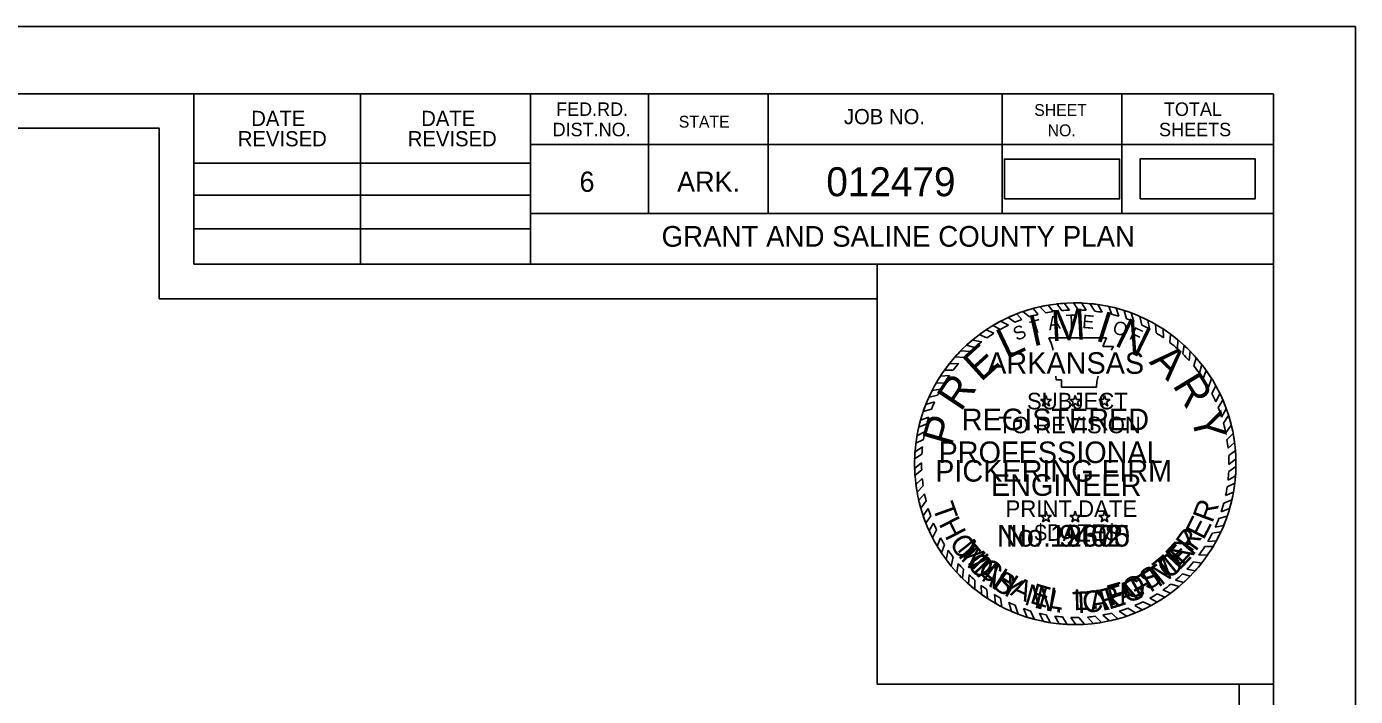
# Model space of a CAD drawing. Extents: x 10700 to 22009, y 10612 to 15552.
# Drawn here: x 16875 to 17646, y 15164 to 15552 of the extents above; entities that cross this region are included whole.
import ezdxf

# ---------------------------------------------------------------- set-up
doc = ezdxf.new("R2010")
doc.units = 0
for name, color, linetype in [('Default', 7, 'Continuous'), ('R_Border', 7, 'Continuous'), ('R_Border Notes', 7, 'Continuous'), ('R_No Plot', 7, 'Continuous'), ('STAMP_PE_CRAFTON', 7, 'Continuous'), ('STAMP_PE_FOSTER', 7, 'Continuous'), ('STAMP_PE_SEAL-INFO', 7, 'Continuous'), ('STAMP_PE_TAEGTMEYER', 7, 'Continuous'), ('STAMP_PE_TXT', 7, 'Continuous'), ('STAMP_PRELIMINARY', 7, 'Continuous')]:
    doc.layers.add(name, color=color, linetype=linetype)

msp = doc.modelspace()

# ---------------------------------------------------------------- linework, layer by layer
at = {"layer": 'Default'}
for points in [[(17442.16, 15452.18), (17508.99, 15452.18), (17508.99, 15475.28), (17442.16, 15475.28)], [(17520.86, 15452.28), (17587.69, 15452.28), (17587.69, 15475.38), (17520.86, 15475.38)]]:
    msp.add_lwpolyline(points, close=True, dxfattribs=at)
at = {"layer": 'R_Border'}
for p, q in [((14436.47, 15513.13), (17598.27, 15513.13)), ((16971.87, 15414.33), (16971.87, 15513.13)), ((17068.67, 15414.33), (17068.67, 15513.13)), ((17167.27, 15513.13), (17167.27, 15414.33)), ((17235.67, 15513.13), (17235.67, 15443.73)), ((17305.07, 15513.13), (17305.07, 15443.73)), ((17440.87, 15513.13), (17440.87, 15443.73)), ((17510.27, 15513.13), (17510.27, 15443.73)), ((17598.27, 13458.53), (17598.27, 15513.13)), ((17598.27, 15483.73), (17167.27, 15483.73)), ((17598.27, 15483.93), (17598.27, 15483.93)), ((16971.87, 15472.93), (17167.27, 15472.93)), ((16971.87, 15454.33), (17167.27, 15454.33)), ((17598.27, 15443.73), (17167.27, 15443.73)), ((17196.87, 15443.73), (17598.27, 15443.73)), ((16971.87, 15434.93), (17167.27, 15434.93)), ((17598.27, 15414.33), (16971.87, 15414.33))]:
    msp.add_line(p, q, dxfattribs=at)
at = {"layer": 'R_No Plot'}
msp.add_line((14312.47, 15552.08), (17645.8, 15552.08), dxfattribs=at)
for points in [[(14312.4, 15552.08), (17645.8, 15552.08), (17645.8, 13418.7), (14312.4, 13418.7)], [(14456.47, 15493.13), (16951.87, 15493.13), (16951.87, 15394.33), (17127.27, 15394.33), (17368.27, 15394.33), (17368.27, 15171.01), (17578.27, 15171.01), (17578.27, 13478.53), (14456.47, 13478.53)], [(17578.27, 14505.83), (14456.47, 14505.83), (14456.47, 15493.13), (16951.87, 15493.13), (16951.87, 15394.33), (17127.27, 15394.33), (17368.27, 15394.33), (17368.27, 15171.01), (17578.27, 15171.01)], [(17368.27, 15414.33), (17598.27, 15414.33), (17598.27, 15171.01), (17368.27, 15171.01)]]:
    msp.add_lwpolyline(points, close=True, dxfattribs=at)
at = {"layer": 'STAMP_PE_SEAL-INFO'}
for p, q in [((17452.87, 15386.89), (17456.68, 15383.83)), ((17458.78, 15388.71), (17461.66, 15385.23)), ((17462.66, 15389.68), (17466.22, 15386.25)), ((17467.48, 15390.64), (17470.47, 15386.97)), ((17472.64, 15391.38), (17475.45, 15387.55)), ((17479.99, 15387.83), (17476.87, 15391.77)), ((17484.97, 15387.88), (17482.18, 15391.98)), ((17489.55, 15387.67), (17486.97, 15391.91)), ((17494.61, 15387.17), (17491.69, 15391.61)), ((17498.87, 15386.52), (17496.29, 15391.07)), ((17504.49, 15385.33), (17502.75, 15389.93)), ((17508.5, 15384.25), (17506.91, 15388.94)), ((17513.02, 15382.78), (17511.61, 15387.57)), ((17440, 15381.34), (17444.64, 15379.08)), ((17444.31, 15383.45), (17448.21, 15380.71)), ((17449.39, 15385.61), (17452.34, 15382.35)), ((17517.21, 15381.18), (17515.76, 15386.14)), ((17521.82, 15379.13), (17520.79, 15384.1)), ((17526.28, 15376.83), (17525.41, 15381.92)), ((17530.15, 15374.57), (17529.76, 15379.57)), ((17427.45, 15373.72), (17432.01, 15371.68)), ((17431.66, 15376.39), (17436.07, 15374.37)), ((17435.52, 15378.83), (17439.85, 15376.6)), ((17468, 15371.67), (17501.45, 15371.67)), ((17469.22, 15368.6), (17468, 15371.67)), ((17501.45, 15371.67), (17499.2, 15366.75)), ((17534.5, 15371.71), (17534.19, 15376.86)), ((17538.1, 15369.04), (17538.45, 15373.91)), ((17416.89, 15364.22), (17422.33, 15363.81)), ((17420.25, 15367.45), (17424.83, 15366.06)), ((17423.68, 15370.45), (17428.98, 15369.45)), ((17470.26, 15365.62), (17469.22, 15368.6)), ((17470.33, 15364.48), (17470.26, 15365.62)), ((17499.2, 15366.75), (17505.52, 15366.75)), ((17505.52, 15366.75), (17504.07, 15364.48)), ((17542.57, 15365.31), (17542.76, 15370.54)), ((17545.69, 15362.39), (17546.39, 15367.37)), ((17549.28, 15358.66), (17549.95, 15363.92)), ((17410.21, 15356.66), (17415.7, 15356.88)), ((17413.66, 15360.77), (17418.88, 15360.39)), ((17552.02, 15355.49), (17553.39, 15360.2)), ((17555.26, 15351.32), (17556.61, 15356.31)), ((17405.08, 15349.52), (17410.24, 15349.86)), ((17407.43, 15352.96), (17412.48, 15352.91)), ((17472.24, 15347.39), (17471.98, 15349.56)), ((17496.62, 15349.56), (17495.84, 15346.47)), ((17557.46, 15348.17), (17559.24, 15352.8)), ((17400.31, 15341.28), (17405.29, 15341.93)), ((17402.62, 15345.51), (17407.51, 15345.71)), ((17475.38, 15347.39), (17472.24, 15347.39)), ((17475.38, 15343.08), (17475.38, 15347.39)), ((17495.68, 15343.08), (17475.38, 15343.08)), ((17495.84, 15346.47), (17495.68, 15343.08)), ((17560.54, 15343.2), (17562.37, 15348.11)), ((17562.54, 15339.53), (17564.8, 15343.97)), ((17396.59, 15333.07), (17401.63, 15334.53)), ((17398.43, 15337.39), (17403.45, 15338.43)), ((17564.85, 15334.69), (17567.11, 15339.54)), ((17566.25, 15331.32), (17568.89, 15335.65)), ((17393.52, 15323.97), (17398.3, 15325.66)), ((17395.09, 15329), (17399.93, 15330.36)), ((17568.2, 15325.83), (17570.91, 15330.57)), ((17569.28, 15322.18), (17572.21, 15326.71)), ((17392.48, 15319.9), (17397.18, 15321.83)), ((17570.61, 15316.6), (17573.79, 15321.06)), ((17395.26, 15312.85), (17390.81, 15310.62)), ((17396.12, 15317.44), (17391.46, 15314.95)), ((17571.3, 15312.8), (17574.83, 15316.33)), ((17571.96, 15307.7), (17575.69, 15311.06)), ((17394.31, 15304.24), (17390.09, 15301.68)), ((17394.67, 15308.49), (17390.31, 15305.68)), ((17572.28, 15303.52), (17576.18, 15306.44)), ((17394.14, 15299.31), (17390.09, 15295.95)), ((17394.21, 15295.24), (17390.29, 15291.99)), ((17572.3, 15294.29), (17576.49, 15297.06)), ((17572.41, 15298.34), (17576.46, 15301.56)), ((17394.54, 15290.29), (17390.83, 15286.72)), ((17571.39, 15285.34), (17575.82, 15287.54)), ((17571.9, 15289.23), (17576.24, 15291.79)), ((17395.06, 15285.99), (17391.52, 15282.26)), ((17395.85, 15281.4), (17392.45, 15277.73)), ((17570.49, 15280.34), (17575.04, 15282.3)), ((17396.78, 15277.22), (17393.66, 15273.07)), ((17398.02, 15272.75), (17395.07, 15268.57)), ((17567.94, 15270.88), (17572.84, 15272.89)), ((17569.41, 15275.83), (17574.13, 15277.84)), ((17399.43, 15268.51), (17396.61, 15264.4)), ((17401.09, 15264.25), (17398.47, 15260.03)), ((17566.59, 15267.09), (17571.42, 15268.4)), ((17402.81, 15260.41), (17400.53, 15255.81)), ((17405.16, 15255.83), (17403.25, 15250.93)), ((17562.84, 15258.58), (17567.72, 15259.26)), ((17564.45, 15261.94), (17569.33, 15262.91)), ((17407.51, 15251.8), (17405.68, 15247.09)), ((17409.54, 15248.68), (17408.44, 15243.16)), ((17558.4, 15250.79), (17563.18, 15250.73)), ((17560.12, 15253.59), (17565.13, 15254.14)), ((17412.35, 15244.77), (17411.33, 15239.47)), ((17415.39, 15241), (17414.52, 15235.8)), ((17551.93, 15241.91), (17556.54, 15241.11)), ((17555.01, 15245.85), (17560.05, 15245.87)), ((17418.41, 15237.62), (17417.79, 15232.4)), ((17421.64, 15234.37), (17421.34, 15229.08)), ((17545.55, 15234.98), (17549.95, 15233.6)), ((17548.09, 15237.57), (17552.86, 15236.72)), ((17425.08, 15231.24), (17425.05, 15225.95)), ((17428.68, 15228.3), (17428.87, 15223.05)), ((17432.06, 15225.8), (17432.42, 15220.62)), ((17534.17, 15225.59), (17538.56, 15223.69)), ((17538.78, 15229.01), (17543.46, 15227.56)), ((17541.49, 15231.26), (17546.2, 15229.97)), ((17436.33, 15222.98), (17436.94, 15217.86)), ((17439.84, 15220.92), (17440.75, 15215.8)), ((17444.65, 15218.43), (17446.21, 15213.21)), ((17522.51, 15218.73), (17527.35, 15216.61)), ((17526.59, 15220.86), (17530.76, 15218.53)), ((17530.74, 15223.31), (17535.23, 15221.35)), ((17448.37, 15216.74), (17450.1, 15211.63)), ((17453.3, 15214.81), (17455.39, 15209.8)), ((17457.4, 15213.46), (17459.66, 15208.57)), ((17462.47, 15212.08), (17464.6, 15207.42)), ((17466.45, 15211.23), (17468.92, 15206.64)), ((17471.45, 15210.41), (17473.85, 15206.01)), ((17475.82, 15209.94), (17478.56, 15205.65)), ((17480.66, 15209.66), (17483.69, 15205.53)), ((17485.26, 15209.65), (17488.7, 15205.69)), ((17490.45, 15209.91), (17493.71, 15206.12)), ((17494.83, 15210.38), (17498.56, 15206.79)), ((17499.28, 15211.07), (17503.17, 15207.68)), ((17504.21, 15212.12), (17507.99, 15208.87)), ((17508.8, 15213.36), (17512.97, 15210.39)), ((17513.73, 15214.99), (17518.16, 15212.3)), ((17517.92, 15216.63), (17522.15, 15214.03))]:
    msp.add_line(p, q, dxfattribs=at)
for radius, start, end in [(93.23, 105.23389, 109.03519), (93.23, 99.75254, 102.77648), (89.14, 98.25799, 101.03289), (93.23, 93.93815, 96.55172), (89.14, 92.11016, 95.03666), (93.23, 87.72979, 90.67067), (89.14, 85.96279, 88.9097), (93.23, 81.97315, 84.82355), (89.14, 79.92642, 82.69597), (93.23, 75.31251, 77.94263), (93.23, 69.60611, 72.30577), (93.23, 117.65441, 120.80988), (93.23, 111.31242, 114.70259), (89.14, 110.30864, 113.16588), (89.14, 104.03521, 107.36155), (89.14, 73.55748, 76.23144), (89.14, 67.62483, 70.50398), (93.23, 63.13288, 66.2704), (89.14, 61.15575, 64.37837), (93.23, 56.90029, 60.09423), (93.23, 123.61993, 126.59063), (89.14, 121.97456, 125.11001), (89.14, 115.68692, 119.15827), (89.14, 54.92383, 58.27016), (93.23, 50.3492, 53.71593), (93.23, 135.40208, 138.30314), (89.14, 133.13306, 136.25623), (93.23, 129.73259, 132.53764), (89.14, 127.52969, 130.96829), (89.14, 48.30163, 52.03953), (93.23, 44.3405, 47.39292), (93.23, 141.60556, 144.44865), (89.14, 139.30101, 142.58729), (89.14, 42.22116, 45.55119), (93.23, 38.12472, 41.23157), (93.23, 147.00719, 149.89904), (89.14, 145.01972, 148.21036), (89.14, 36.13503, 39.53106), (93.23, 31.96138, 35.42937), (93.23, 152.86398, 155.51889), (89.14, 151.03153, 153.57304), (89.14, 29.90321, 33.66454), (93.23, 25.93909, 29.01247), (93.23, 158.40766, 161.07015), (89.14, 156.34018, 159.23194), (89.14, 23.77322, 27.22114), (93.23, 19.95381, 23.31409), (89.14, 162.43309, 165.00133), (89.14, 17.68022, 21.42509), (93.23, 13.84205, 17.44468), (93.23, 164.3068, 166.89395), (89.14, 11.54445, 15.23639), (93.23, 170.0003, 172.68778), (89.14, 167.90481, 170.90393), (89.14, 5.7599, 9.06056), (93.23, 7.58519, 10.86211), (93.23, 175.74093, 178.2066), (89.14, 173.73, 176.47337), (89.14, 359.73289, 3.06392), (93.23, 1.72155, 4.72681), (93.23, 181.72508, 184.16255), (89.14, 179.64537, 182.26333), (93.23, 355.71562, 358.95694), (93.23, 187.42037, 190.19271), (89.14, 185.45389, 188.23401), (89.14, 353.86319, 357.12742), (93.23, 349.83047, 353.08845), (89.14, 191.22736, 193.98583), (89.14, 348.07782, 351.34355), (93.23, 193.03695, 195.99732), (89.14, 196.96751, 199.83526), (89.14, 341.77699, 345.09248), (93.23, 343.89247, 347.03502), (93.23, 198.89671, 201.62812), (89.14, 202.77613, 205.47915), (89.14, 335.6038, 339.18578), (93.23, 337.38367, 340.99332), (93.23, 204.54793, 207.43282), (89.14, 208.78826, 211.79343), (89.14, 329.55488, 333.20757), (93.23, 331.40371, 334.93315), (93.23, 210.86355, 213.65709), (89.14, 214.18375, 217.27474), (89.14, 323.58513, 327.44069), (93.23, 325.44052, 328.98725), (93.23, 216.61154, 219.49098), (89.14, 220.39088, 223.30564), (89.14, 316.65308, 320.37109), (93.23, 318.28455, 321.80429), (93.23, 222.47995, 225.38008), (89.14, 226.24938, 229.24068), (89.14, 310.77436, 314.31605), (93.23, 312.45177, 315.66328), (93.23, 228.36648, 231.34802), (89.14, 232.22904, 234.93361), (89.14, 304.82299, 308.51428), (93.23, 306.37206, 310.20799), (93.23, 234.29502, 236.94517), (89.14, 238.22227, 240.83529), (93.23, 240.1977, 242.86128), (89.14, 244.32043, 246.94859), (89.14, 292.87452, 296.11851), (89.14, 299.07679, 302.17235), (93.23, 300.62101, 303.87026), (93.23, 246.57598, 249.15579), (89.14, 250.34912, 253.12157), (93.23, 252.59667, 255.32518), (89.14, 256.50505, 259.11916), (89.14, 262.37828, 265.20115), (89.14, 268.3215, 271.27698), (89.14, 274.61565, 277.44863), (89.14, 280.34588, 283.58137), (89.14, 286.64233, 289.97826), (93.23, 288.57086, 291.97334), (93.23, 294.64808, 298.21662), (93.23, 258.44328, 261.13983), (93.23, 264.19784, 267.10092), (93.23, 270.25484, 273.33609), (93.23, 276.42389, 279.43574), (93.23, 282.31994, 285.37019)]:
    msp.add_arc((17483.27, 15298.76), radius, start, end, dxfattribs=at)
at = {"layer": 'STAMP_PE_TXT'}
for p, q in [((17465.07, 15334.47), (17463.09, 15335.91)), ((17463.09, 15335.91), (17465.54, 15335.91)), ((17464.31, 15332.14), (17465.07, 15334.47)), ((17466.3, 15333.58), (17464.31, 15332.14)), ((17465.54, 15335.91), (17466.3, 15338.25)), ((17466.3, 15338.25), (17467.05, 15335.91)), ((17468.28, 15332.14), (17466.3, 15333.58)), ((17467.05, 15335.91), (17469.5, 15335.91)), ((17469.5, 15335.91), (17467.52, 15334.47)), ((17467.52, 15334.47), (17468.28, 15332.14)), ((17482.05, 15334.47), (17480.07, 15335.91)), ((17480.07, 15335.91), (17482.52, 15335.91)), ((17481.29, 15332.14), (17482.05, 15334.47)), ((17483.27, 15333.58), (17481.29, 15332.14)), ((17482.52, 15335.91), (17483.27, 15338.25)), ((17483.27, 15338.25), (17484.03, 15335.91)), ((17485.26, 15332.14), (17483.27, 15333.58)), ((17484.03, 15335.91), (17486.48, 15335.91)), ((17486.48, 15335.91), (17484.5, 15334.47)), ((17484.5, 15334.47), (17485.26, 15332.14)), ((17499.03, 15334.47), (17497.04, 15335.91)), ((17497.04, 15335.91), (17499.5, 15335.91)), ((17498.27, 15332.14), (17499.03, 15334.47)), ((17500.25, 15333.58), (17498.27, 15332.14)), ((17499.5, 15335.91), (17500.25, 15338.25)), ((17500.25, 15338.25), (17501.01, 15335.91)), ((17502.24, 15332.14), (17500.25, 15333.58)), ((17501.01, 15335.91), (17503.46, 15335.91)), ((17503.46, 15335.91), (17501.48, 15334.47)), ((17501.48, 15334.47), (17502.24, 15332.14)), ((17465.07, 15267.4), (17463.09, 15268.84)), ((17463.09, 15268.84), (17465.54, 15268.84)), ((17464.31, 15265.07), (17465.07, 15267.4)), ((17466.3, 15266.51), (17464.31, 15265.07)), ((17465.54, 15268.84), (17466.3, 15271.18)), ((17466.3, 15271.18), (17467.05, 15268.84)), ((17468.28, 15265.07), (17466.3, 15266.51)), ((17467.05, 15268.84), (17469.5, 15268.84)), ((17469.5, 15268.84), (17467.52, 15267.4)), ((17467.52, 15267.4), (17468.28, 15265.07)), ((17482.05, 15267.4), (17480.07, 15268.84)), ((17480.07, 15268.84), (17482.52, 15268.84)), ((17481.29, 15265.07), (17482.05, 15267.4)), ((17483.27, 15266.51), (17481.29, 15265.07)), ((17482.52, 15268.84), (17483.27, 15271.18)), ((17483.27, 15271.18), (17484.03, 15268.84)), ((17485.26, 15265.07), (17483.27, 15266.51)), ((17484.03, 15268.84), (17486.48, 15268.84)), ((17486.48, 15268.84), (17484.5, 15267.4)), ((17484.5, 15267.4), (17485.26, 15265.07)), ((17499.03, 15267.4), (17497.04, 15268.84)), ((17497.04, 15268.84), (17499.5, 15268.84)), ((17498.27, 15265.07), (17499.03, 15267.4)), ((17500.25, 15266.51), (17498.27, 15265.07)), ((17499.5, 15268.84), (17500.25, 15271.18)), ((17500.25, 15271.18), (17501.01, 15268.84)), ((17502.24, 15265.07), (17500.25, 15266.51)), ((17501.01, 15268.84), (17503.46, 15268.84)), ((17503.46, 15268.84), (17501.48, 15267.4)), ((17501.48, 15267.4), (17502.24, 15265.07))]:
    msp.add_line(p, q, dxfattribs=at)
at = {"layer": 'STAMP_PRELIMINARY'}
msp.add_circle((17483.27, 15298.76), 93.23, dxfattribs=at)

# ---------------------------------------------------------------- texts
at = {"layer": 'R_Border'}
for s, height, p in [('DATE', 8.792, (17005.25, 15494.5)), ('DATE', 8.792, (17103.85, 15494.5)), ('FED.RD.', 7.819, (17182.07, 15500.33)), ('JOB NO.', 8.792, (17349.07, 15495.53)), ('SHEET', 6.84, (17459.47, 15500.33)), ('TOTAL', 7.819, (17534.67, 15500.33)), ('DIST.NO.', 7.819, (17180.07, 15488.53)), ('STATE', 6.84, (17253.27, 15493.53)), ('NO.', 6.84, (17467.27, 15488.53)), ('SHEETS', 7.819, (17531.87, 15488.53)), ('REVISED', 8.792, (16997.45, 15482.7)), ('REVISED', 8.792, (17096.05, 15482.7)), ('6', 11.72, (17195.67, 15456.33)), ('ARK.', 11.723, (17252.27, 15456.33))]:
    msp.add_text(s, height=height, rotation=360, dxfattribs=at).set_placement(p)
at = {"layer": 'R_Border Notes'}
for s, height, p in [('012479', 16.8, (17338.85, 15453.78)), ('GRANT AND SALINE COUNTY PLAN', 12, (17243.29, 15424.52))]:
    msp.add_text(s, height=height, dxfattribs=at).set_placement(p)
at = {"layer": 'STAMP_PE_CRAFTON'}
for s, rotation, p in [('No. 12370', 360, (17437.89, 15250.73)), ('T', 310.74416, (17412.93, 15247.74)), ('N', 49.24107, (17546.1, 15238.98)), ('O', 317.64216, (17419.61, 15239.62)), ('N', 324.45371, (17428.07, 15231.78)), ('T', 34.11362, (17529.04, 15225.15)), ('O', 41.83906, (17537.63, 15231.16)), ('Y', 331.16864, (17438.4, 15224.61)), ('F', 28.78207, (17519.89, 15220.05)), ('N', 347.47515, (17458.94, 15215.45)), ('C', 6.01169, (17487.99, 15212.17)), ('R', 14.81888, (17498.95, 15213.32)), ('A', 20.51248, (17510.08, 15216.32)), ('.', 356.89262, (17471.24, 15212.68))]:
    msp.add_text(s, height=12.5, rotation=rotation, dxfattribs=at).set_placement(p)
at = {"layer": 'STAMP_PE_FOSTER'}
for s, height, rotation, p in [('No. 9402', 12.5, 360, (17443.13, 15250.73)), ('R', 12, 54.5031, (17550.52, 15246.87)), ('M', 12, 308.33902, (17414.43, 15248.98)), ('E', 12, 46.96131, (17543.28, 15238.66)), ('I', 12, 314.18423, (17422.41, 15239.6)), ('C', 12, 319.87327, (17425.95, 15236.07)), ('T', 12, 39.41938, (17534.7, 15231.16)), ('H', 12, 327.72349, (17435.25, 15228.71)), ('O', 12, 23.71897, (17514.07, 15219.58)), ('S', 12, 31.72336, (17525.18, 15224.88)), ('A', 12, 335.72761, (17445.05, 15222.89)), ('E', 12, 343.5779, (17456.43, 15218.19)), ('L', 12, 350.81148, (17467.01, 15215.41)), ('L', 12, 1.26658, (17482.41, 15213.84)), ('F', 12, 15.86908, (17503.62, 15216.31)), ('.', 12, 6.80354, (17492.88, 15214.43))]:
    msp.add_text(s, height=height, rotation=rotation, dxfattribs=at).set_placement(p)
at = {"layer": 'STAMP_PE_TAEGTMEYER'}
for s, rotation, p in [('T', 289.64597, (17400.22, 15273.86)), ('R', 69.57001, (17562.73, 15263.9)), ('H', 296.73386, (17403.82, 15264.02)), ('E', 63.0984, (17557.74, 15254.09)), ('O', 303.77078, (17409.75, 15252.94)), ('No. 19605', 360, (17437.89, 15250.73)), ('Y', 53.99864, (17551.05, 15244.68)), ('M', 314.20329, (17416.3, 15243.42)), ('E', 46.80938, (17543.66, 15236.53)), ('A', 321.0594, (17425.91, 15233.78)), ('M', 39.30005, (17533.25, 15227.74)), ('S', 327.82385, (17434.17, 15227.34)), ('T', 31.46601, (17524.27, 15222.31)), ('N', 344.27273, (17453.14, 15217.28)), ('T', 3.00609, (17481.92, 15211.96)), ('A', 8.98261, (17492.38, 15212.52)), ('E', 17.68363, (17502.77, 15214.07)), ('G', 23.30524, (17513.27, 15217.38)), ('.', 350.64643, (17465.27, 15213.96))]:
    msp.add_text(s, height=12.5, rotation=rotation, dxfattribs=at).set_placement(p)
at = {"layer": 'STAMP_PE_TXT'}
for s, height, rotation, p in [('T', 7.81, 16.311, (17458.49, 15373.52)), ('A', 7.81, 9.0679, (17468.11, 15376.05)), ('T', 7.81, 1.82479, (17477.98, 15377.34)), ('E', 7.81, 355.20019, (17487.08, 15377.43)), ('O', 7.81, 342.25065, (17504.35, 15374.66)), ('S', 7.81, 23.5541, (17449.26, 15369.8)), ('F', 7.81, 335.00755, (17514, 15371.28)), ('ARKANSAS', 12.5, 360, (17432.2, 15350.86)), ('REGISTERED', 12.5, 360, (17417.44, 15318.17)), ('PROFESSIONAL', 12.5, 360, (17403.96, 15299.15)), ('ENGINEER', 12.5, 360, (17434.36, 15280.14))]:
    msp.add_text(s, height=height, rotation=rotation, dxfattribs=at).set_placement(p)
at = {"layer": 'STAMP_PRELIMINARY'}
for s, height, rotation, p in [('M', 18, 3.10738, (17469.63, 15369.72)), ('I', 18, 342.31637, (17494.31, 15370.39)), ('I', 18, 12.52485, (17458.65, 15366.62)), ('N', 18, 333.9382, (17505.38, 15367.65)), ('L', 18, 25.51305, (17443.36, 15359.03)), ('E', 18, 42.35784, (17428.54, 15345.72)), ('A', 18, 315.65789, (17525.72, 15357.4)), ('R', 18, 56.22922, (17416.98, 15328.4)), ('R', 18, 301.38306, (17539.4, 15344.25)), ('SUBJECT', 9.6, 360, (17455.27, 15330.25)), ('P', 18, 73.91301, (17411.49, 15308.16)), ('TO REVISION', 9.6, 360, (17438.63, 15316.4)), ('Y', 18, 283.25926, (17550.29, 15326.39)), ('PICKERING FIRM', 12.5, 360, (17402.01, 15288.39)), ('PRINT DATE', 9.6, 360, (17442.85, 15267.91)), ('$DATE$', 9.6, 360, (17459.62, 15254.07))]:
    msp.add_text(s, height=height, rotation=rotation, dxfattribs=at).set_placement(p)

doc.saveas('drawing.dxf')
